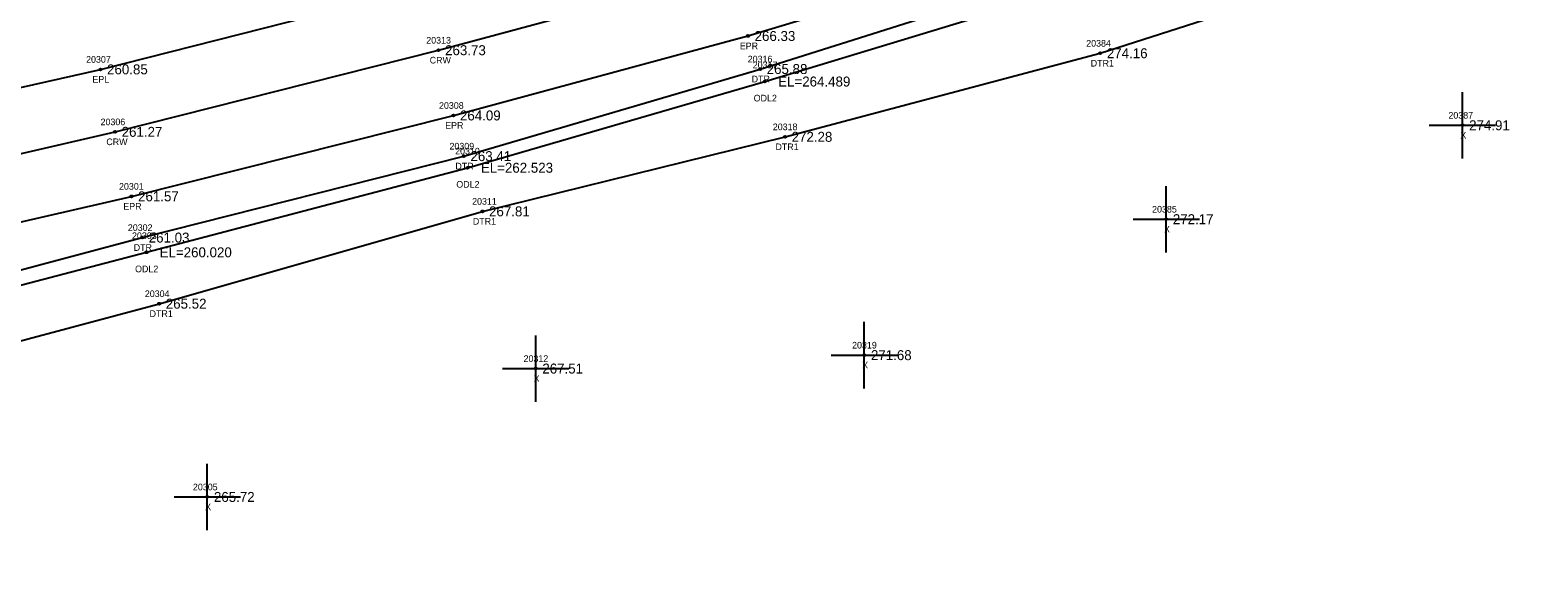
# Model space of a CAD drawing. Extents: x 2275563 to 2277161, y 1075719 to 1076412.
# Drawn here: x 2276701.4 to 2276928.6, y 1076060.8 to 1076143.1 of the extents above; entities that cross this region are included whole.
import ezdxf

# ---------------------------------------------------------------- set-up
doc = ezdxf.new("R2010")
doc.units = 0
for name, color, linetype in [('RD_DTM_BkLn1', 7, 'Continuous'), ('RD_EX_H2O', 7, 'Continuous'), ('RD_EX_H2O_txCode', 7, 'Continuous'), ('RD_EX_Misc', 7, 'Continuous'), ('RD_EX_Misc_txCode', 7, 'Continuous'), ('RD_EX_Road', 7, 'Continuous'), ('RD_EX_Road_txCode', 7, 'Continuous'), ('RD_EX_TX_H2O_ELEV', 7, 'Continuous'), ('RD_EX_TX_Misc_ELEV', 7, 'Continuous'), ('RD_EX_TX_Road_ELEV', 7, 'Continuous'), ('RD_HC_Survey_ELEV', 7, 'Continuous'), ('RD_HC_Survey_txCode', 7, 'Continuous'), ('RD_SMD_Locator', 7, 'Continuous')]:
    doc.layers.add(name, color=color, linetype=linetype)

msp = doc.modelspace()

# ---------------------------------------------------------------- linework, layer by layer
at = {"layer": 'RD_DTM_BkLn1'}
msp.add_lwpolyline([(2276380.47, 1076073.8), (2276432.36, 1076079.4), (2276487.41, 1076086.42), (2276535.62, 1076093.32), (2276578.15, 1076099.97), (2276622.03, 1076107.93), (2276668.51, 1076117.27), (2276714.2, 1076127.81), (2276762.94, 1076140.11), (2276806.88, 1076151.96), (2276854.94, 1076166.29), (2276899.73, 1076180.7), (2276952.88, 1076198.57), (2277000.46, 1076214.72), (2277057.1, 1076234.01), (2277134.93, 1076261.07)], dxfattribs=at)
at = {"layer": 'RD_EX_H2O'}
for points in [[(2276577.32, 1076064.99), (2276581.11, 1076068.71), (2276607.06, 1076074.47), (2276628.35, 1076084.13), (2276659.02, 1076095.85), (2276671.39, 1076099.39), (2276718.28, 1076111.88), (2276766.76, 1076124.15), (2276811.4, 1076137.27), (2276858.53, 1076152.16), (2276905.48, 1076167.47), (2276958.61, 1076184.59), (2277007.29, 1076200.4), (2277063.09, 1076219.53), (2277141.85, 1076245.35)], [(2276577.32, 1076064.99), (2276608.07, 1076069.56), (2276629.89, 1076080.39), (2276660.01, 1076094.12), (2276672.11, 1076097.43), (2276718.92, 1076109.66), (2276767.33, 1076122.4), (2276812.13, 1076135.39), (2276859.85, 1076149.89), (2276906.21, 1076164.41), (2276959.66, 1076181.81), (2277008.45, 1076198), (2277064.73, 1076216.97), (2277142.57, 1076243.16)], [(2276577.32, 1076064.99), (2276585.61, 1076060.77), (2276608.72, 1076065.79), (2276630.67, 1076076.21), (2276642.12, 1076079.44), (2276661.39, 1076087.16), (2276674.74, 1076089.6), (2276720.85, 1076101.92), (2276769.56, 1076115.83), (2276815.16, 1076127.06), (2276862.66, 1076139.65), (2276909.53, 1076154.75), (2276961.42, 1076172.61), (2277010.89, 1076191.18), (2277066.25, 1076211.87), (2277143.49, 1076241.1)]]:
    msp.add_lwpolyline(points, dxfattribs=at)
at = {"layer": 'RD_EX_Misc'}
for p, q in [((2276917.25, 1076123.8), (2276917.25, 1076133.8)), ((2276912.25, 1076128.8), (2276922.25, 1076128.8)), ((2276872.6, 1076109.65), (2276872.6, 1076119.65)), ((2276867.6, 1076114.65), (2276877.6, 1076114.65)), ((2276827.11, 1076089.17), (2276827.11, 1076099.17)), ((2276777.59, 1076087.15), (2276777.59, 1076097.15)), ((2276822.11, 1076094.17), (2276832.11, 1076094.17)), ((2276772.59, 1076092.15), (2276782.59, 1076092.15)), ((2276728.1, 1076067.81), (2276728.1, 1076077.81)), ((2276723.1, 1076072.81), (2276733.1, 1076072.81))]:
    msp.add_line(p, q, dxfattribs=at)
at = {"layer": 'RD_EX_Road'}
for points in [[(2276379.21, 1076084.39), (2276432.25, 1076089.28), (2276486.22, 1076095.98), (2276535.61, 1076103.32), (2276577.16, 1076110.11), (2276620.86, 1076117.78), (2276666.21, 1076126.9), (2276712, 1076137.22), (2276761.13, 1076149.72), (2276804.56, 1076161.71), (2276851.24, 1076175.53), (2276896.93, 1076190.53), (2276950.19, 1076208.22), (2276997.45, 1076224.3), (2277053.81, 1076243.77), (2277132.14, 1076270.77)], [(2276381.27, 1076063.04), (2276433.15, 1076069.16), (2276488.59, 1076076.23), (2276537.45, 1076083.34), (2276579.64, 1076090.09), (2276624.07, 1076098.24), (2276670.54, 1076107.46), (2276716.67, 1076118.09), (2276765.18, 1076130.28), (2276809.58, 1076142.25), (2276856.93, 1076156.58), (2276903.53, 1076171.63), (2276957.27, 1076189.46), (2277005.85, 1076206.01), (2277060.98, 1076225.07), (2277139.5, 1076252.36)]]:
    msp.add_lwpolyline(points, dxfattribs=at)
at = {"layer": 'RD_SMD_Locator'}
for centre in [(2276809.58, 1076142.25), (2276762.94, 1076140.11), (2276862.66, 1076139.65), (2276712, 1076137.22), (2276811.4, 1076137.27), (2276812.13, 1076135.39), (2276765.18, 1076130.28), (2276917.25, 1076128.8), (2276714.2, 1076127.81), (2276815.16, 1076127.06), (2276766.76, 1076124.15), (2276767.33, 1076122.4), (2276716.67, 1076118.09), (2276769.56, 1076115.83), (2276872.6, 1076114.65), (2276718.28, 1076111.88), (2276718.92, 1076109.66), (2276720.85, 1076101.92), (2276827.11, 1076094.17), (2276777.59, 1076092.15), (2276728.1, 1076072.81)]:
    msp.add_circle(centre, 0.15, dxfattribs=at)

# ---------------------------------------------------------------- texts
at = {"layer": 'RD_EX_H2O_txCode'}
for s, p in [('20384', (2276860.55, 1076140.65)), ('20316', (2276809.54, 1076138.27)), ('20317', (2276810.3, 1076137.39)), ('DTR1', (2276861.23, 1076137.65)), ('DTR', (2276810.13, 1076135.27)), ('ODL2', (2276810.44, 1076132.39)), ('20318', (2276813.32, 1076128.06)), ('20309', (2276764.6, 1076125.15)), ('DTR1', (2276813.72, 1076125.06)), ('20310', (2276765.45, 1076124.4)), ('DTR', (2276765.49, 1076122.15)), ('ODL2', (2276765.63, 1076119.4)), ('20311', (2276768.01, 1076116.83)), ('DTR1', (2276768.12, 1076113.83)), ('20302', (2276716.13, 1076112.88)), ('20303', (2276716.76, 1076111.66)), ('DTR', (2276717.02, 1076109.88)), ('ODL2', (2276717.22, 1076106.66)), ('20304', (2276718.69, 1076102.92)), ('DTR1', (2276719.41, 1076099.92))]:
    msp.add_text(s, height=1, dxfattribs=at).set_placement(p)
at = {"layer": 'RD_EX_Misc_txCode'}
for s, p in [('20387', (2276915.13, 1076129.8)), ('X', (2276916.93, 1076126.8)), ('20385', (2276870.48, 1076115.65)), ('X', (2276872.28, 1076112.65)), ('20312', (2276775.76, 1076093.15)), ('20319', (2276825.27, 1076095.17)), ('X', (2276826.79, 1076092.17)), ('X', (2276777.28, 1076090.15)), ('20305', (2276725.94, 1076073.81)), ('X', (2276727.78, 1076070.81))]:
    msp.add_text(s, height=1, dxfattribs=at).set_placement(p)
at = {"layer": 'RD_EX_Road_txCode'}
for s, p in [('EPR', (2276808.35, 1076140.25)), ('20307', (2276709.84, 1076138.22)), ('EPL', (2276710.79, 1076135.22)), ('20308', (2276763.02, 1076131.28)), ('EPR', (2276763.95, 1076128.28)), ('20301', (2276714.8, 1076119.09)), ('EPR', (2276715.45, 1076116.09))]:
    msp.add_text(s, height=1, dxfattribs=at).set_placement(p)
at = {"layer": 'RD_EX_TX_H2O_ELEV'}
for s, p in [('274.16', (2276863.66, 1076138.9)), ('265.88', (2276812.4, 1076136.52)), ('EL=264.489', (2276814.13, 1076134.64)), ('272.28', (2276816.16, 1076126.31)), ('263.41', (2276767.76, 1076123.4)), ('EL=262.523', (2276769.33, 1076121.65)), ('267.81', (2276770.56, 1076115.08)), ('261.03', (2276719.28, 1076111.13)), ('EL=260.020', (2276720.92, 1076108.91)), ('265.52', (2276721.85, 1076101.17))]:
    msp.add_text(s, height=1.5, dxfattribs=at).set_placement(p)
at = {"layer": 'RD_EX_TX_Misc_ELEV'}
for s, p in [('274.91', (2276918.25, 1076128.05)), ('272.17', (2276873.6, 1076113.9)), ('271.68', (2276828.11, 1076093.42)), ('267.51', (2276778.59, 1076091.4)), ('265.72', (2276729.1, 1076072.06))]:
    msp.add_text(s, height=1.5, dxfattribs=at).set_placement(p)
at = {"layer": 'RD_EX_TX_Road_ELEV'}
for s, p in [('266.33', (2276810.58, 1076141.5)), ('260.85', (2276713, 1076136.47)), ('264.09', (2276766.18, 1076129.53)), ('261.57', (2276717.67, 1076117.34))]:
    msp.add_text(s, height=1.5, dxfattribs=at).set_placement(p)
at = {"layer": 'RD_HC_Survey_ELEV'}
for s, p in [('263.73', (2276763.94, 1076139.36)), ('261.27', (2276715.2, 1076127.06))]:
    msp.add_text(s, height=1.5, dxfattribs=at).set_placement(p)
at = {"layer": 'RD_HC_Survey_txCode'}
for s, p in [('20313', (2276761.1, 1076141.11)), ('CRW', (2276761.62, 1076138.11)), ('20306', (2276712.02, 1076128.81)), ('CRW', (2276712.89, 1076125.81))]:
    msp.add_text(s, height=1, dxfattribs=at).set_placement(p)

doc.saveas('drawing.dxf')
